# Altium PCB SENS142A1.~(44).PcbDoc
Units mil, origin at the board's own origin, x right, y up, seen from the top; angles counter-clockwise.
Board outline 2760 x 2518.85 mil, 4 copper layers (Top Layer, Signal Layer 1, Signal Layer 2, Bottom Layer), stack 62.2 mil thick; 50 components, 21 nets, 98 pads, 340 vias.
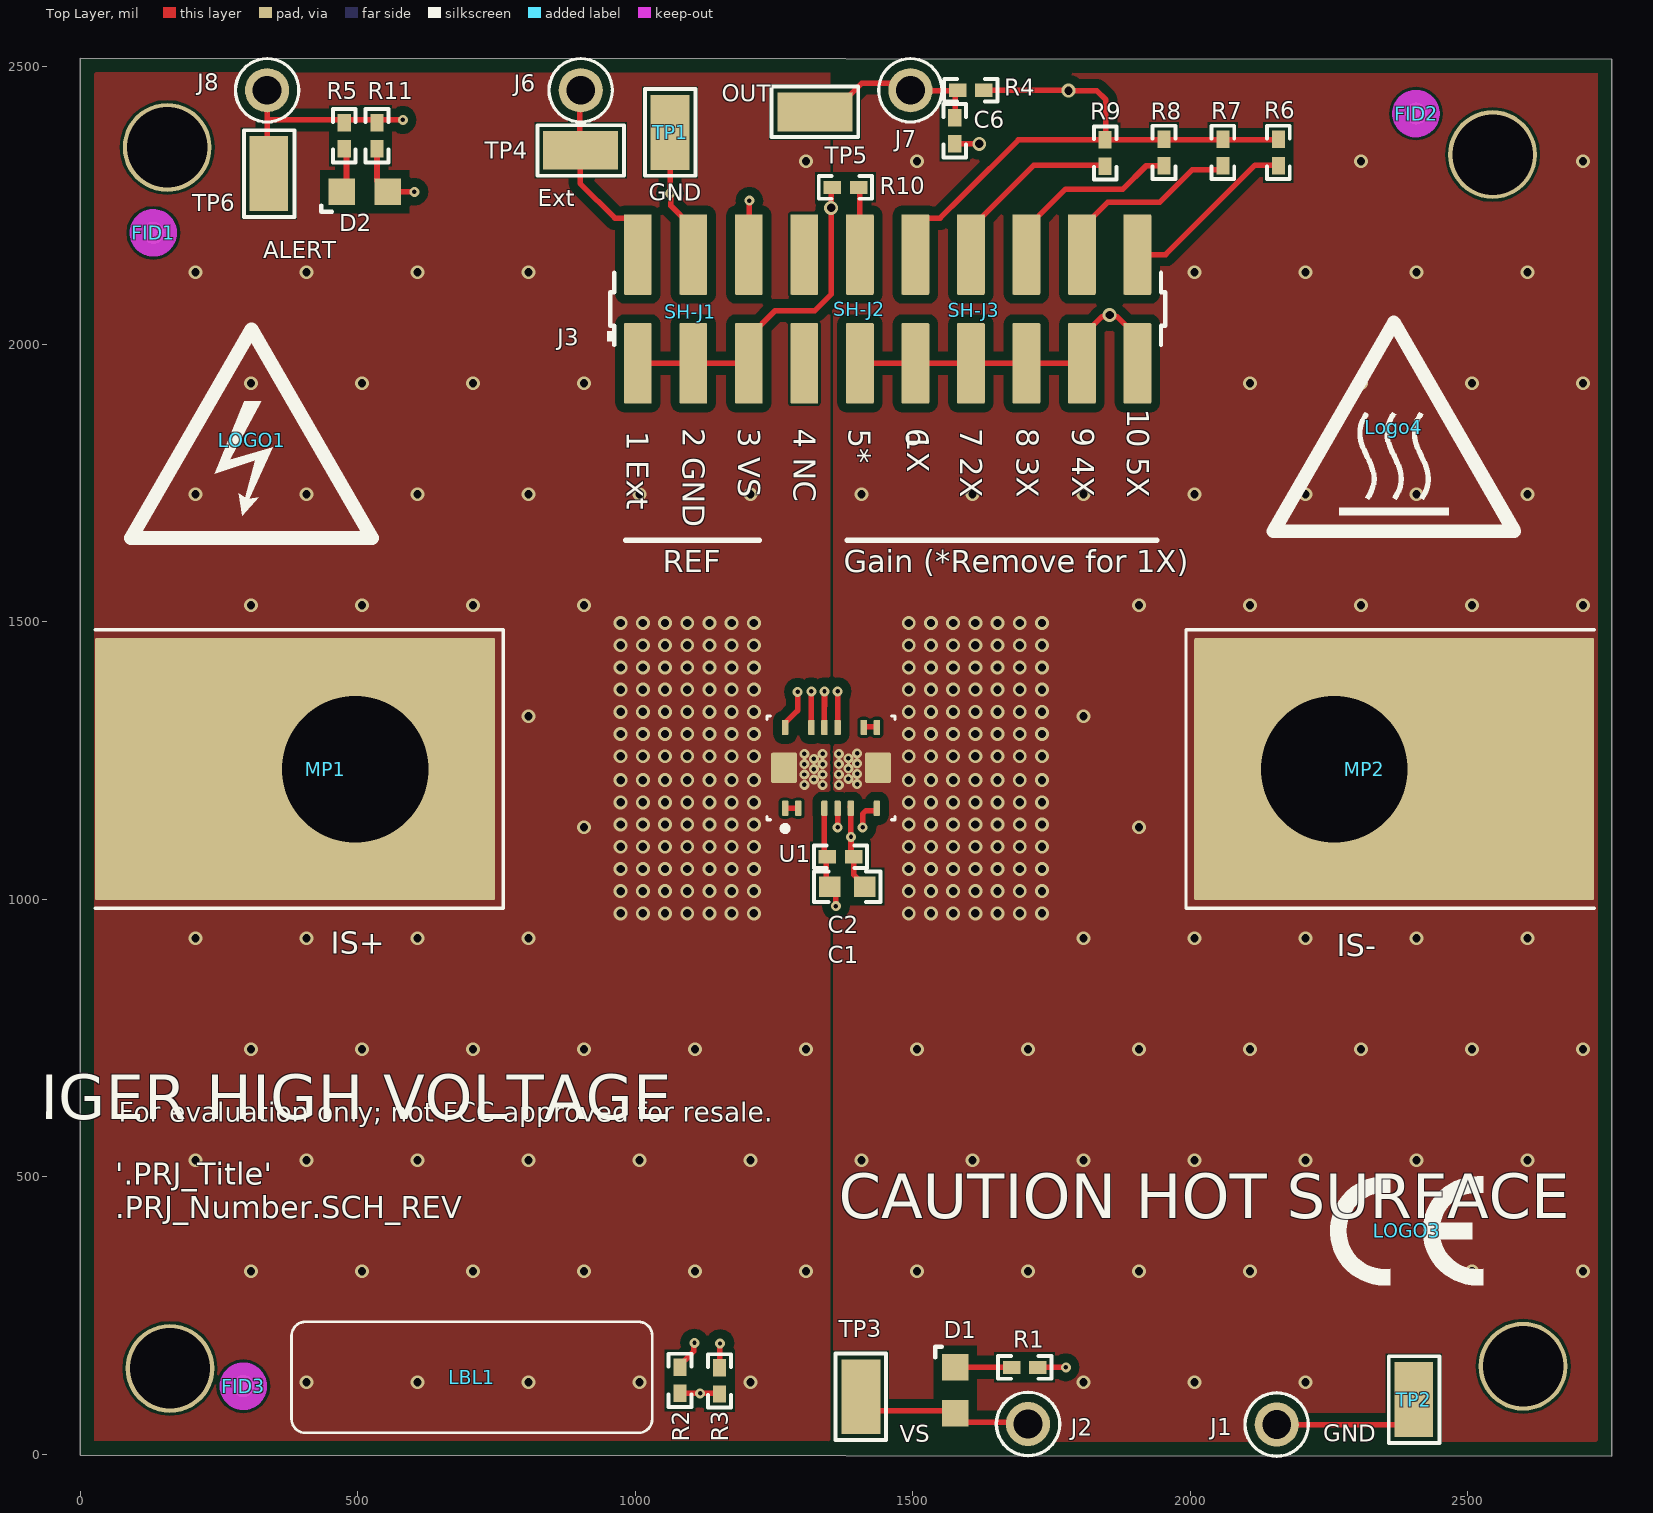
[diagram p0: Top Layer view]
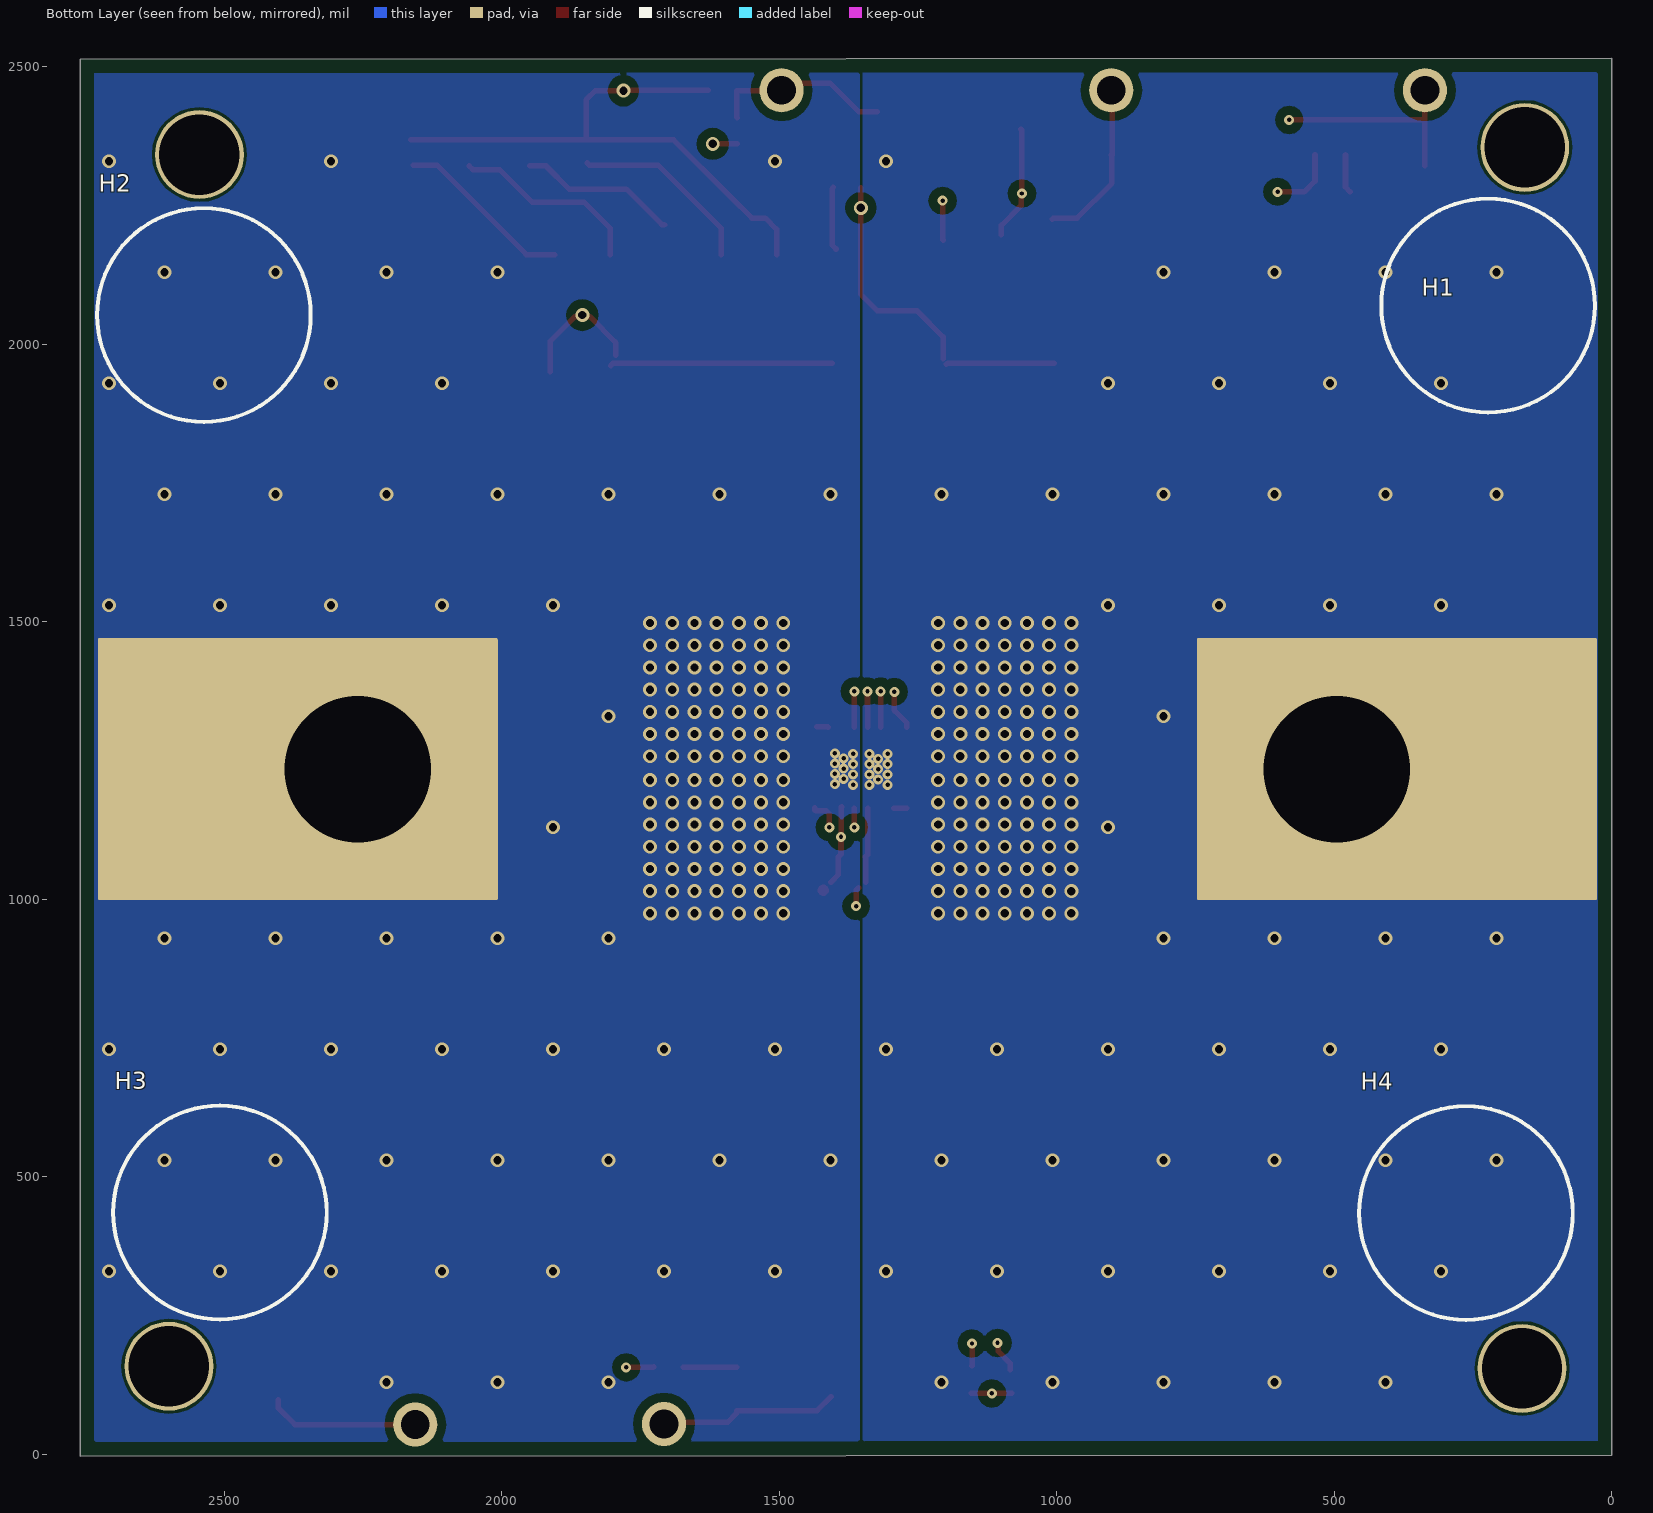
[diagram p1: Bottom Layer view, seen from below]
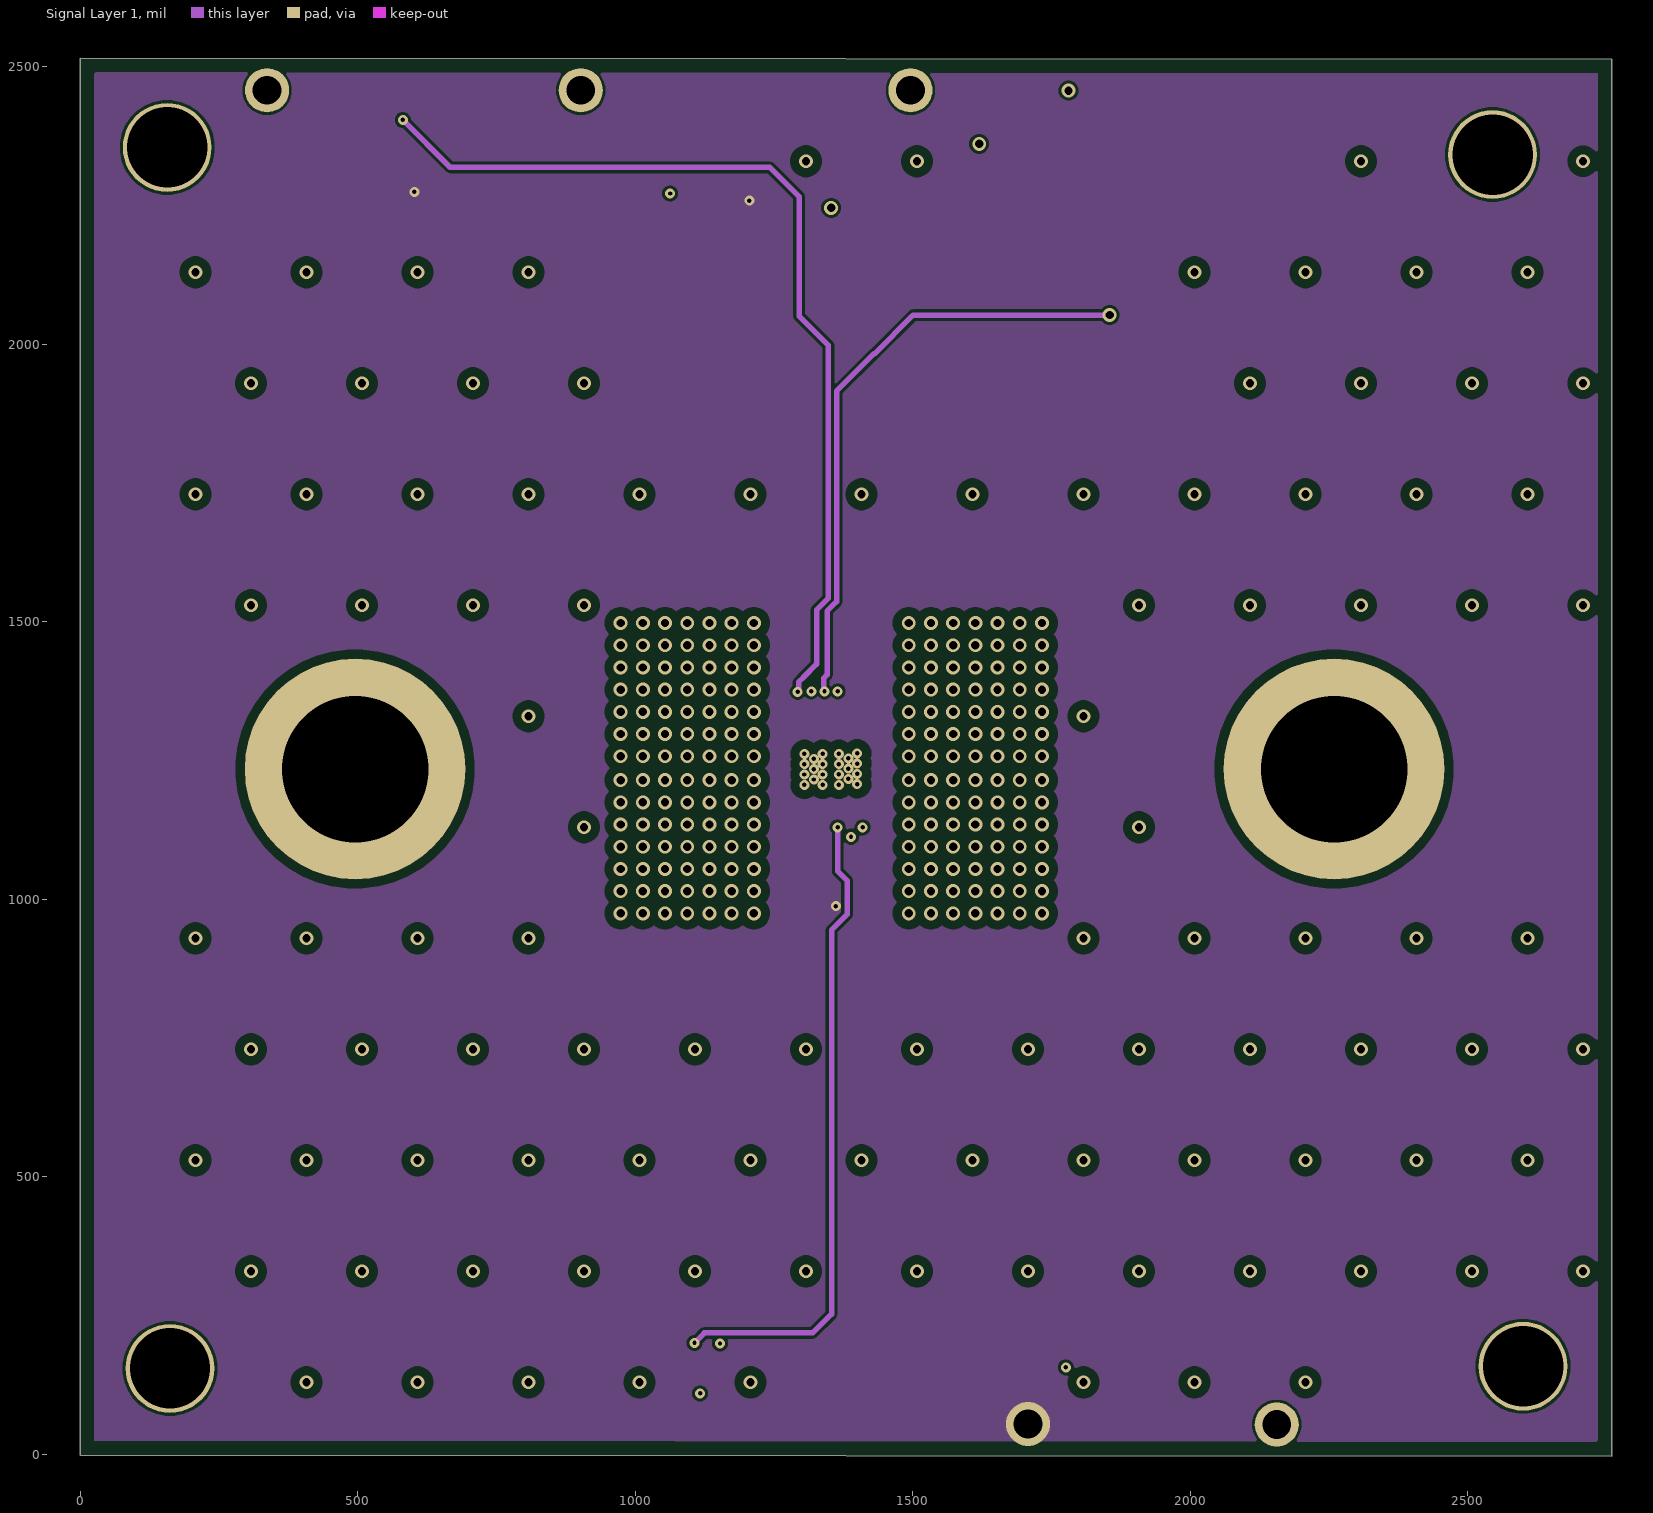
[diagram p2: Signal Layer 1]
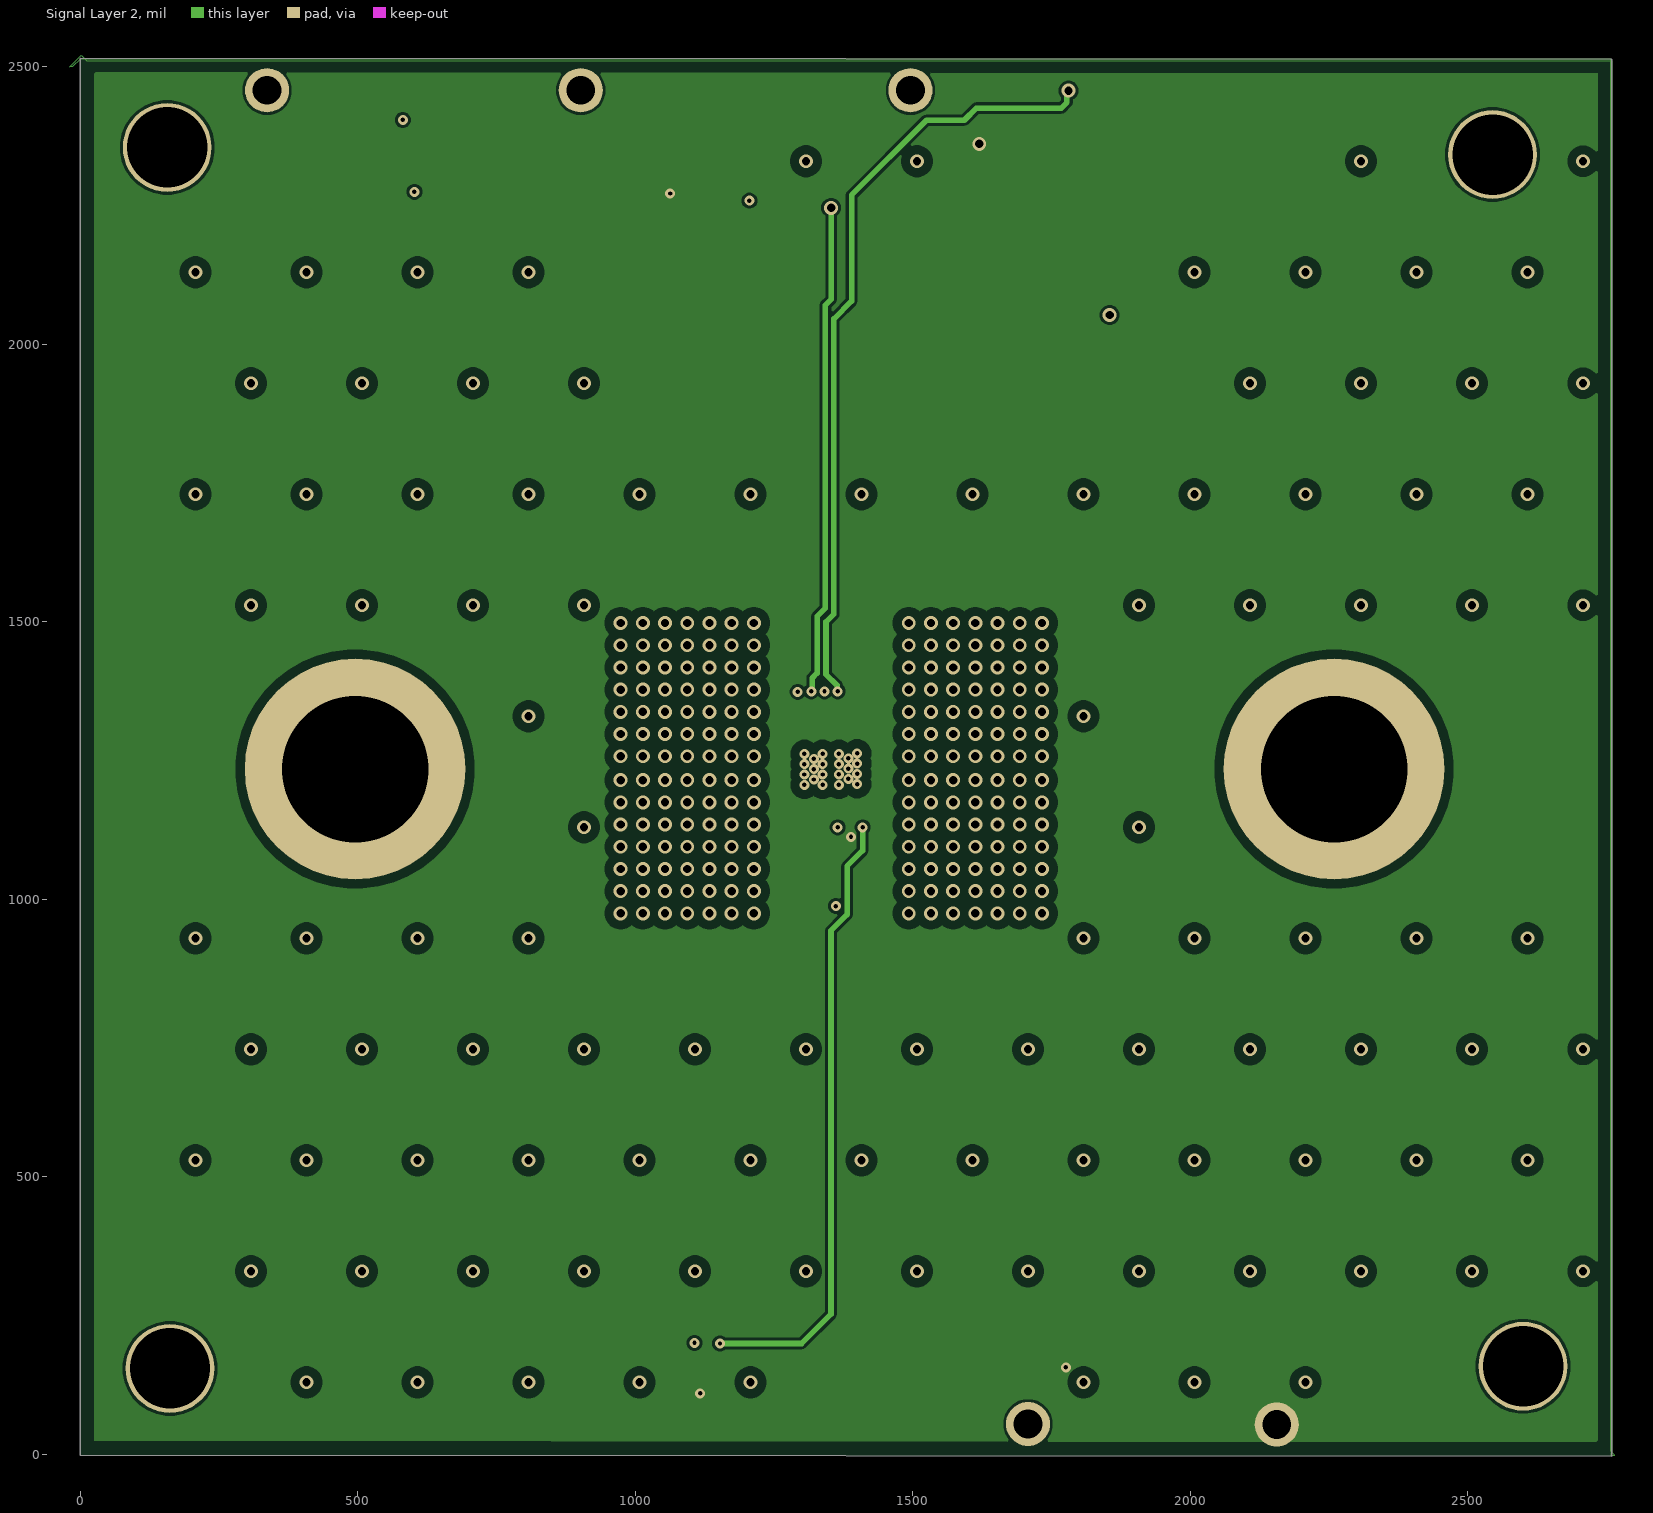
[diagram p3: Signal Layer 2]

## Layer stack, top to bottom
Top Solder: solder mask 0.4, Solder Resist, Dk 3.5
Top Layer: signal copper 2.8
Dielectric1: dielectric 17, FR-4, Dk 4.2
Signal Layer 1: signal copper 2.8
Dielectric 2: core 17, FR-4, Dk 4.2
Signal Layer 2: signal copper 2.8
Dielectric 3: dielectric 17, FR-4, Dk 4.2
Bottom Layer: signal copper 2.8
Bottom Solder: solder mask 0.4, Solder Resist, Dk 3.5

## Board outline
0,-1 0,2516 2760,2514.15 2760,-2.85

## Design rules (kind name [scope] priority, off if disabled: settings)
AcuteAngle [All] p1: minimum=4.50000000000000E+0001 checktracksonly=FALSE
AssemblyTestPointUsage [All] p1: valid=2
BoardOutlineClearance BoardOutlineClearance_MountingHoles [OnCopper and InComponentClass('Mounting Holes')] p1: gap=14 ignorepadtopadclearanceinfootprint=FALSE
BoardOutlineClearance BoardOutlineClearance_Poly [OnCopper and IsPoly] p2: gap=25 ignorepadtopadclearanceinfootprint=FALSE
BoardOutlineClearance [OnCopper and Not InComponentClass('Logo') and not InComponentClass('FiducialMark') and not InRegion(1000,500,4000,800) and not InPoly] p3: gap=15 ignorepadtopadclearanceinfootprint=FALSE
Clearance Clearance_Keepouts [((IsTrack Or IsArc) And Not InPoly) And IsFree and IsKeepOut vs ((IsTrack Or IsArc) And Not InPoly) And IsFree and IsKeepOut] p1: gap=0 ignorepadtopadclearanceinfootprint=FALSE
Clearance Clearance_IS+ [InNet('IS+') vs (InNet('OUT') OR InNet('FB') OR InNet('REF') OR InNet('GND') OR InNet('VS') OR InNet('NC4') OR InNet('NC6') OR InNet('ALERT') OR InNet('NetD1_2') OR InNet('NetD2_2') OR InNet('NetJ3_10') OR InNet('NetJ3_14') OR InNet('NetJ3_16') OR InNet('NetJ3_18') OR InNet('NetJ3_20') OR InNet('OUT_FLT') OR InNet('Ext_REF'))] p2: gap=16 ignorepadtopadclearanceinfootprint=TRUE
Clearance Clearance_IS- [InNet('IS-') vs (InNet('OUT') OR InNet('FB') OR InNet('REF') OR InNet('GND') OR InNet('VS') OR InNet('NC4') OR InNet('NC6') OR InNet('ALERT') OR InNet('NetD1_2') OR InNet('NetD2_2') OR InNet('NetJ3_10') OR InNet('NetJ3_14') OR InNet('NetJ3_16') OR InNet('NetJ3_18') OR InNet('NetJ3_20') OR InNet('OUT_FLT') OR InNet('Ext_REF'))] p3: gap=16 ignorepadtopadclearanceinfootprint=TRUE
Clearance Clearance_FiducialMark [IsKeepOut and InComponentClass('FiducialMark') vs IsPad and InComponentClass('FiducialMark')] p4: gap=0 ignorepadtopadclearanceinfootprint=FALSE
Clearance [All] p5: gap=5 ignorepadtopadclearanceinfootprint=TRUE
ComponentClearance ComponentClearance_MountingHoles_FiducialMarks [InComponentClass('Mounting Holes') vs InComponentClass('FiducialMark')] p1: gap=50 collisioncheckmode=3 verticalgap=10 showdistances=FALSE
ComponentClearance ComponentClearance_Shunt [InComponentClass('Header') vs InComponentClass('Shunt')] p2: gap=0 collisioncheckmode=3 verticalgap=0 showdistances=FALSE
ComponentClearance ComponentClearance_Logo [InComponentClass('Logo')] p3: gap=20 collisioncheckmode=3 verticalgap=10 showdistances=FALSE
ComponentClearance ComponentClearance_ScrewToNut [(HasFootprint('NY PMS 440 0025 PH')) vs (HasFootprint('Keystone_1902C'))] p4: gap=5 collisioncheckmode=3 verticalgap=10 showdistances=FALSE
ComponentClearance ComponentClearance_MountingHoles [InComponentClass('Mounting Holes')] p5: gap=250 collisioncheckmode=3 verticalgap=100000 showdistances=FALSE
ComponentClearance ComponentClearance_SmallPassives [HasFootprint('0201*') or HasFootprint('0402*') or HasFootprint('0508') or HasFootprint('0603*') or HasFootprint('0612') or HasFootprint('0805*') or HasFootprint('0815*') or HasFootprint('0830*') or HasFootprint('1206*') or HasFootprint('1210*') or HasFootprint('1808*') or HasFootprint('1812*') or HasFootprint('1825*') or HasFootprint('2010*') or HasFootprint('2220*') or HasFootprint('2225*') or HasFootprint('2512*') or HasFootprint('2728*') or HasFootprint('3518*') vs HasFootprint('0201*') or HasFootprint('0402*') or HasFootprint('0508') or HasFootprint('0603*') or HasFootprint('0612') or HasFootprint('0805*') or HasFootprint('0815*') or HasFootprint('0830*') or HasFootprint('1206*') or HasFootprint('1210*') or HasFootprint('1808*') or HasFootprint('1812*') or HasFootprint('1825*') or HasFootprint('2010*') or HasFootprint('2220*') or HasFootprint('2225*') or HasFootprint('2512*') or HasFootprint('2728*') or HasFootprint('3518*')] p6: gap=14.96 collisioncheckmode=3 verticalgap=10 showdistances=FALSE
ComponentClearance ComponentClearance_THtoSMT [IsThruComponent vs IsSMTComponent] p7: gap=40 collisioncheckmode=3 verticalgap=30 showdistances=FALSE
ComponentClearance ComponentClearance_THtoTH [IsThruComponent vs IsThruComponent] p8: gap=30 collisioncheckmode=3 verticalgap=30 showdistances=FALSE
ComponentClearance [All] p9: gap=30 collisioncheckmode=3 verticalgap=10 showdistances=FALSE
DiffPairsRouting [All] p1: maxlimit=100 minlimit=10 mostfreqgap=10 toplayer_minwidth=15 toplayer_maxwidth=15 toplayer_prefwidth=15 midlayer1_minwidth=15 midlayer1_maxwidth=15 midlayer1_prefwidth=15 midlayer2_minwidth=15 midlayer2_maxwidth=15 midlayer2_prefwidth=15 bottomlayer_minwidth=15 bottomlayer_maxwidth=15 bottomlayer_prefwidth=15 maxuncoupledlength=1000
FabricationTestPointUsage TestPointUsage [All] p1: valid=2 allowmultiple=FALSE
FabricationTestpoint Testpoint [All] p1: side=3 testpointundercomponent=TRUE minsize=40 maxsize=100 preferedsize=60 minholesize=0 maxholesize=40 preferedholesize=32 testpointgrid=1 allowsidetop=TRUE allowsidebottom=TRUE usegrid=TRUE gridtolerance=0.01
FanoutControl Fanout_LCC [IsLCC] p1: bgadir=Out bgaviamode=Centered fanoutstyle=Auto fanoutdirection=Alternating viagrid=1 // Fanout_LCC (Default Rule)
FanoutControl Fanout_BGA [IsBGA] p2: bgadir=Out bgaviamode=Centered fanoutstyle=Auto fanoutdirection=Alternating viagrid=1 // Fanout_BGA (Default Rule)
FanoutControl Fanout_Default [All] p4: bgadir=Out bgaviamode=Centered fanoutstyle=Auto fanoutdirection=Alternating viagrid=1 // Fanout_Default (Default Rule)
FanoutControl Fanout_Small [(CompPinCount < 5)] p5: bgadir=Out bgaviamode=Centered fanoutstyle=Auto fanoutdirection=OutThenIn viagrid=1 // Fanout_Small (Default Rule)
HoleSize [All] p1: absolutevalues=TRUE maxlimit=251 minlimit=8 maxpercent=80.000 minpercent=20.000
HoleToHoleClearance [All] p1: gap=8 allowstackedmicrovias=TRUE
MinimumAnnularRing MinimumAnnularRing_ThermalPadVias [IsVia and InAnyComponent] p1: minimumring=5
MinimumAnnularRing [All] p2: minimumring=5
MinimumSolderMaskSliver MinimumSolderMaskSliver_Logo [InComponentClass('Logo') vs InComponentClass('Logo')] p1: minsoldermaskwidth=0.7
MinimumSolderMaskSliver [All] p2: minsoldermaskwidth=4
PlaneConnect [All] p1: planeconnectstyle=Relief reliefexpansion=10 reliefentries=4 reliefconductorwidth=10 reliefairgap=10
PolygonConnect PolygonConnect_Trace [InNet('NetJ1_5') OR InNet('NetJ1_3')] p1: connectstyle=Direct reliefconductorwidth=10 reliefentries=4 polygonreliefangle="90 Angle" airgapwidth=10
PolygonConnect [All] p2: thpad.connectstyle=Direct thpad.reliefconductorwidth=10 thpad.reliefentries=4 thpad.polygonreliefangle="90 Angle" thpad.airgapwidth=10 smdpad.connectstyle=Relief smdpad.reliefconductorwidth=10 smdpad.reliefentries=2 smdpad.polygonreliefangle="90 Angle" smdpad.airgapwidth=10 via.connectstyle=Direct via.reliefconductorwidth=10 via.reliefentries=4 via.polygonreliefangle="90 Angle" via.airgapwidth=10
RoutingVias [All] p1: holewidth=10 width=20 viastyle="Through Hole" minholewidth=4 minwidth=15 maxholewidth=40 maxwidth=65
SilkToBoardRegionClearance [Not ((IsComment or IsDesignator) And (Hide <> 'False')) and not InRegion(1000,500,4000,800)] p1:
SilkToSilkClearance SilkToSilkClearance_Pb-FreeLogo [(HasFootprint('Pb-Free_Overlay_Medium') OR HasFootprint('Pb-Free_Overlay_Small')) vs (HasFootprint('Pb-Free_Overlay_Medium') OR HasFootprint('Pb-Free_Overlay_Small'))] p1: silktosilkclearance=0
SilkToSilkClearance [All] p2: silktosilkclearance=3.94
SilkToSolderMaskClearance SilkToComponentPadClearance [(IsPad or IsFill or IsRegion) and InAnycomponent] p1: minsilkscreentomaskgap=5 clearancetoexposedcopper=TRUE
SilkToSolderMaskClearance "Silk to Solder Mask Opening" [All] p2: minsilkscreentomaskgap=3.94 clearancetoexposedcopper=FALSE
SolderMaskExpansion [All] p1: expansion=1.97 istentingtop=FALSE
UnRoutedNet [All] p1: checkbadconnections=TRUE
Width [All] p1: maxlimit=100 minlimit=5 preferedwidth=10 checkconnectedcopper=TRUE
13 further rules are at their usual default settings.

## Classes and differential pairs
component class Label: LBL1
component class Shunt: SH-J1 SH-J2 SH-J3
component class Header: J3
component class SENS142A1: "ALERT BUS" C1 C2 C6 D1 D2 J1 J2 J3 J6 J7 J8 MP1 MP2 q R1 R2 R3 R4 R5 R6 R7 R8 R9 R10 R11 SH-J1 SH-J2 SH-J3 SW2 SW? TP1 TP2 TP3 TP4 TP5 TP6 U1
component class SENS142A1_HW: FID1 FID2 FID3 H1 H2 H3 H4 LBL1 LOGO1 Logo2 LOGO3 Logo4 ZZ1 ZZ2 ZZ3 ZZ4
component class FiducialMark: FID1 FID2 FID3
component class AssemblyNote: ZZ1 ZZ2 ZZ3 ZZ4

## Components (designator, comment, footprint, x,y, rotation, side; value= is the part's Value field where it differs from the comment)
C1 "C1608X6S1H105K080AC" 0603 1382.19,1023 r0 top value=1uF
C2 "GRM155R71H104ME14D" 0402 1370,1077 r0 top value=0.1uF
C6 "CGA2B3X7S2A103K050BB" 0402 1576,2385 r90 top value=0.01uF
D1 "POWER" VAOL-0805_White 1577,115.66 r90 top
D2 "ALERT" VAOL-0805_White 513,2275 r180 top
FID1 "Fiducial" Fiducial10-20 132,2201.12 r0 top
FID2 "Fiducial" Fiducial10-20 2407,2416 r0 top
FID3 "Fiducial" Fiducial10-20 294,123 r0 top
H1 "SJ61A2" Bumpon_SJ61A2 223,2070 r180 bottom
H2 "SJ61A2" Bumpon_SJ61A2 2537,2053 r180 bottom
H3 "SJ61A2" Bumpon_SJ61A2 2508,436 r180 bottom
H4 "SJ61A2" Bumpon_SJ61A2 263,435 r180 bottom
J1 "" FP-3-331272-8_PIN_RCPT-MFG 2156,54 r0 top
J2 "" FP-3-331272-8_PIN_RCPT-MFG 1708,55 r180 top
J3 "TSM-110-01-L-DV-P" CONN_TSM-110-01-T-DV-P 1455,2064 r90 top
J6 "" FP-3-331272-8_PIN_RCPT-MFG 902,2458 r0 top
J7 "" FP-3-331272-8_PIN_RCPT-MFG 1496,2458 r0 top
J8 "" FP-3-331272-8_PIN_RCPT-MFG 337,2458 r0 top
LBL1 "THT-14-423-10" Label_650x200 706,139 r180 top
LOGO1 "DANGER HIGH VOLTAGE" IEC_HighVoltage_Medium 309,1827 r0 top
Logo2 "FCC disclaimer" FCC_disclaimer 3340,617.12 r90 top
LOGO3 "CE Mark" CE_Mark_5mm 2390,403 r0 top
Logo4 "CAUTION HOT SURFACE" IEC_HotSurface_Medium 2367,1851 r0 top
MP1 "CB70-14-190" FP-CB70-14-190_CONN_TERM_RECT_LUG-MFG -30,1235 r0 top
MP2 "CB70-14-190" FP-CB70-14-190_CONN_TERM_RECT_LUG-MFG 2785,1235 r180 top
R1 "CRCW040210K0FKED" 0402 1702,157 r180 top value=10.0k
R2 "RC0402JR-070RL" 0402 1081,133.62 r270 top value=0
R3 "RC0402JR-070RL" 0402 1152,132.62 r270 top value=0
R4 "RC0402JR-070RL" 0402 1605,2458 r180 top value=0
R5 "CRCW040210K0FKED" 0402 476,2376 r90 top value=10.0k
R6 "CRCW040220K0FKED" 0402 2159,2346 r270 top value=20.0k
R7 "CRCW040215K0FKED" 0402 2059,2346 r270 top value=15.0k
R8 "CRCW040210K0FKED" 0402 1953,2346 r90 top value=10.0k
R9 "CRCW04024K99FKED" 0402 1847,2345 r270 top value=4.99k
R10 "CRCW04024K99FKED" 0402 1379,2283 r0 top value=4.99k
R11 "CRCW040210K0FKED" 0402 535,2376 r90 top value=10.0k
SH-J1 "SPC02SYAN" SPC02SYAN 1099,2059 r270 top value=1x2
SH-J2 "SPC02SYAN" SPC02SYAN 1404,2063 r90 top value=1x2
SH-J3 "SPC02SYAN" SPC02SYAN 1610,2062 r90 top value=1x2
TP1 "GND" Testpoint_Keystone_Miniature 1063,2382 r90 top
TP2 "GND" Testpoint_Keystone_Miniature 2403,99 r90 top
TP3 "VS" Testpoint_Keystone_Miniature 1407,104 r270 top
TP4 "Ext_REF" Testpoint_Keystone_Miniature 902,2350 r0 top
TP5 "OUT" Testpoint_Keystone_Miniature 1324,2419 r180 top
TP6 "" Testpoint_Keystone_Miniature 340,2308 r90 top
U1 "INA750AIREMR" REM0014B-MFG 1353,1237.12 r90 top
ZZ1 "This Assembly Note is for PCB labels only" AssemblyNoteLabel -115,3802.12 r0 top
ZZ2 "These assemblies are ESD sensitive, ESD precautions shall be observed." AssemblyNote -115,3693.24 r0 top
ZZ3 "These assemblies must be clean and free from flux and all contaminants. Use of no clean flux is not acceptable." AssemblyNote -115,3604.68 r0 top
ZZ4 "These assemblies must comply with workmanship standards IPC-A-610 Class 2, unless otherwise specified." AssemblyNote -115,3516.12 r0 top

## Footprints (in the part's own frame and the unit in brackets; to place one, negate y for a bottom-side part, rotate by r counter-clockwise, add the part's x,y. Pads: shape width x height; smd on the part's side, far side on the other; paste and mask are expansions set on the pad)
0402 [mm] "0402 from SM-752 data"
  rect 0.8x0.6 smd: 1(-0.6,0) 2(0.6,0)
  silkscreen extent -1.22,-0.52 1.22,0.52, body extent -0.55,-0.3 0.55,0.3, height 0.6
0603 [mm] "0603 from SM-752 data"
  rect 1x0.95 smd: 1(-0.8,0) 2(0.8,0)
  silkscreen extent -1.52,-0.69 1.52,0.69, body extent -0.87,-0.47 0.87,0.47, height 1
AssemblyNote [mil] "Assembly Note"
AssemblyNoteLabel [mil] "Assembly Note for PCB Labels"
Bumpon_SJ61A2 [mil] "3M Hemispherical Bumpon transparent"
  round 1 on Mech4: 0(0,0)
  silkscreen extent -192,-192 192,192, body extent -193,-193 193,193, height 250
CE_Mark_5mm [mil] "Minimum text height for CE Mark"
  silkscreen extent -138,-98 138,98
CONN_TSM-110-01-T-DV-P [mil]
  rrect8% 145x50 smd: 1(-98,450) 2(98,450) 3(-98,350) 4(98,350) 5(-98,250) 6(98,250) 7(-98,150) 8(98,150) 9(-98,50) 10(98,50) 11(-98,-50) 12(98,-50) 13(-98,-150) 14(98,-150) 15(-98,-250) 16(98,-250) 17(-98,-350) 18(98,-350) 19(-98,-450) 20(98,-450)
  silkscreen extent -65,-500 65,506, body extent -145,-500 145,500, height 380
FCC_disclaimer [mil]
Fiducial10-20 [mm]
  round 1 smd mask+0.5: 1(0,0)
  Top Layer keep-out circle w1.178: c0,0 r0.5
FP-3-331272-8_PIN_RCPT-MFG [mm]
  round 2.02 hole 1.32 paste-1000 mask+0: 1(0,0)
  silkscreen extent -1.45,-1.45 1.45,1.45, body extent -1.11,-1.11 1.11,1.11, height 0.25
FP-CB70-14-190_CONN_TERM_RECT_LUG-MFG [mm]
  rrect1% 18.3x12 smd paste-1000 mask+0: 1(10.6,0)
  rrect1% 18.3x12 smd far side paste-1000 mask+0: 1(10.6,0)
  round 10.1 hole 6.7 unplated paste+0 mask+0: 1(13.35,0)
  silkscreen extent 1.45,-6.38 20.12,6.38, body extent -20.1,-6.35 20.1,6.35, height 0.25
IEC_HighVoltage_Medium [mil]
  silkscreen extent -217,-176 217,200
IEC_HotSurface_Medium [mil]
  silkscreen extent -217,-188 217,188
Label_650x200 [mil] "Thermal Transfer Label"
  round 1 on Mech13: 0(0,0)
  silkscreen extent -325,-100 325,100, body extent -325,-100 325,100, height 1
REM0014B-MFG [mm]
  rrect33% 0.7x0.3 smd paste+0 mask+0: 1(-1.85,2.1) 2(-1.85,1.5) 3(-1.85,0.3) 4(-1.85,-0.3) 5(-1.85,-0.9) 6(-1.85,-2.1) 8(1.85,-2.1) 9(1.85,-1.5) 10(1.85,-0.3) 11(1.85,0.3) 12(1.85,0.9) 13(1.85,2.1)
  rrect17% 1.4x1.2 smd paste-1000 mask-1000: 7(0,-2.15) 14(0,2.15)
  silkscreen extent -2.9,-2.93 2.37,2.93, body extent -2.3,-2.85 2.3,2.85, height 0.25
SPC02SYAN [mil] "SULLINS"
  round 1 on Mech3: 0(0,0)
  body extent -98,-47 99,47, height 366
Testpoint_Keystone_Miniature [mil] "Miniature SMT test point"
  rect 135x70 smd: 1(0,0)
  silkscreen extent -78,-46 78,45, body extent -52,-20 52,20, height 61
VAOL-0805_White [mm] "Visual Communications"
  rect 1.2x1.2 smd: 1(-1.05,0) 2(1.05,0)
  silkscreen extent 1.5,0.63 2,0.91, body extent -1.05,-0.67 1.05,0.67, height 1.1

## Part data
C1: library part CMP-0007029-4, "CAP, CERM, 1 uF, 50 V, +/- 10%, X6S, 0603", Cap_Case=0603, Manufacturer=TDK, Supplier Part Number 1=445-7424-1-ND, TempCo=X6S, Tolerance_%=10%, Value1="0.005522 ohm", Value2=50V, ValueDisplayed=1uF
C2: library part CMP-0006675-2, "CAP, CERM, 0.1 uF, 50 V, +/- 20%, X7R, 0402", Cap_Case=0402, Manufacturer=MuRata, Supplier Part Number 1=490-10701-1-ND, TempCo=X7R, Tolerance_%=20%, Value1=Unknown, Value2=50V, ValueDisplayed=0.1uF
C6: library part CMP-0006333-1, "CAP, CERM, 0.01 uF, 100 V, +/- 10%, X7S, AEC-Q200 Grade 1, 0402", Cap_Case=0402, Manufacturer=TDK, Supplier Part Number 1=445-6910-1-ND, TempCo=X7S, Tolerance_%=10%, Value1="0.410191 ohm", Value2=100V, ValueDisplayed=0.01uF
D1 D2: library part CMP-0002885-2, "LED, White, SMD", Color=White, Manufacturer="Visual Communications Company, LLC", PartNumber=VAOL-S8WR4, Value1=W, Value2=2.925V
FID1 FID2 FID3: library part CMP-0077181-1, "Fiducial mark.  There is nothing to buy or mount.", Manufacturer=N/A
H1 H2 H3 H4: library part CMP-0003622-1, "Bumpon, Hemisphere, 0.375 X 0.235, Black", Manufacturer=3M, Supplier Part Number 1=SJ5748-0-ND
J1 J2 J6 J7 J8: library part CMP-0086763-1, "CONN PIN RCPT .018-.021 SOLDER", Current_A=5A, Manufacturer="TE Connectivity", PartNumber=3-331272-8
J3: library part CMP-0075600-2, "Header, 2.54mm, 10x2, Gold, SMT", Color=Black, Current_A=5.4A, Manufacturer=Samtec, Supplier Part Number 1=SAM8739-ND, Voltage_V=475V
LBL1: library part CMP-0003625-1, "Thermal Transfer Printable Labels, 0.650\" W x 0.200\" H - 10,000 per roll", Manufacturer=Brady, Supplier Part Number 1=97C5133
LOGO1: library part CMP-0074835-1, "IEC 61010-1 High Voltage Warning"
Logo2: library part CMP-0074847-1, "FCC_disclaimer"
LOGO3: library part CMP-0074844-1
Logo4: library part CMP-0074837-2, "IEC 61010-1 Hot Surface Warning", Manufacturer="Texas Instruments"
MP1 MP2: library part CMP-0121463-2, "Terminal Connector Rectangular Lug, Grounding 1/4 Stud", Current_A=90A, Digikey Part Number=298-CB70-14-190-ND, Manufacturer=Panduit, Operating Temperature Range="to +90°C", Voltage_V=600V
R1 R5 R8 R11: library part CMP-0025958-3, "RES, 10.0 k, 1%, 0.063 W, AEC-Q200 Grade 0, 0402", Manufacturer=Vishay-Dale, Power_W=63mW, Supplier Part Number 1=541-10.0KLCT-ND, TempCo="100 ppm/C", Tolerance_%=1%, Value2=0.063W, Value_Code=10k0, ValueDisplayed=10.0k
R2 R3 R4: library part CMP-0027004-2, "RES, 0, 5%, 0.063 W, 0402", Manufacturer="Yageo America", Power_W=63mW, Supplier Part Number 1=311-0.0JRCT-ND, TempCo="200 ppm/C", Tolerance_%=5%, Value2=0.063W, Value_Code=0000, ValueDisplayed=0
R6: library part CMP-0026162-1, "RES, 20.0 k, 1%, 0.063 W, 0402", Manufacturer=Vishay-Dale, Power_W=63mW, Supplier Part Number 1=541-20.0KLCT-ND, TempCo="100 ppm/C", Tolerance_%=1%, Value2=0.063W, Value_Code=20k0, ValueDisplayed=20.0k
R7: library part CMP-0026027-2, "RES, 15.0 k, 1%, 0.063 W, 0402", Manufacturer=Vishay-Dale, Power_W=63mW, Supplier Part Number 1=541-15.0KLCT-ND, TempCo="100 ppm/C", Tolerance_%=1%, Value2=0.063W, Value_Code=15k0, ValueDisplayed=15.0k
R9 R10: library part CMP-0026414-1, "RES, 4.99 k, 1%, 0.063 W, 0402", Manufacturer=Vishay-Dale, Power_W=63mW, Supplier Part Number 1=541-4.99KLCT-ND, TempCo="100 ppm/C", Tolerance_%=1%, Value2=0.063W, Value_Code=4k99, ValueDisplayed=4.99k
SH-J1 SH-J2 SH-J3: library part CMP-0003642-1, "Shunt, 100mil, Flash Gold, Black", Manufacturer="Sullins Connector Solutions", Supplier Part Number 1=S9001-ND
TP1 TP2 TP3 TP4 TP5 TP6: library part CMP-0055152-1, "Test Point, Miniature, SMT", Manufacturer=Keystone, PartNumber=5015, Supplier Part Number 1=36-5015TR-ND
U1: library part CMP-0122809-2, "-4V to 110V, Bidirectional, Ultra-Precise, Current Sense Amplifier with Enhanced PWM Rejection and 35A EZShuntTM Technology", Input Offset Voltage=65mV, Manufacturer="Texas Instruments", Max Supply Voltage=5.5V, Min Supply Voltage=2.7V, Nominal Supply Current=3.5mA, Operating Temperature Range="-55°C to +150°C", Output Current Per Channel=25A
ZZ1: library part CMP-0003616-3
ZZ2: library part CMP-0077236-1
ZZ3: library part CMP-0077237-1
ZZ4: library part CMP-0077238-1

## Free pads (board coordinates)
  round 160 hole 145: 3(157,2355) 3(162,155) 3(2545,2342.12) 3(2600,159)

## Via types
v1: diameter 25, hole 15, Top Layer to Bottom Layer, tented both sides, 302 vias
v2: diameter 18, hole 8, Top Layer to Bottom Layer, tented both sides, 38 vias

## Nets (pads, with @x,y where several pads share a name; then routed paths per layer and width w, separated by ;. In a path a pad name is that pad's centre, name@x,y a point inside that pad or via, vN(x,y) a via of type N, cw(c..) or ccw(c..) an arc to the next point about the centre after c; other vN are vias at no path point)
ALERT: J8.1 R5.2 R11.2 TP6.1 U1.13 | length 2150.9
  Top Layer w10: TP6.1@337,2322 337,2406 ; J8.1@337,2446 337,2406 ; v2(581.45,2404.5) 338.5,2404.5 337,2406 ; U1.13 1270.32,1317.83 1293,1340.51 1293,1348 ; v2(1293,1374) 1293.26,1373.74 1293.26,1348
  Signal Layer 1 w10: v2(581.45,2404.5) 666.95,2319 1243,2319 1295.59,2266.41 1295.59,2050.97 1348.19,1998.38 1348.19,1543 1327,1521.81 1327,1424.25 1303.87,1401.13 ; v2(1293,1374) 1294.53,1375.53 1294.53,1391.53 1304,1401
Ext_REF: J3.2 J6.1 TP4.1 | length 301.7
  Top Layer w10: TP4.1@900,2342 J6.1@900,2458 ; TP4.1@902,2342 901,2341 901,2290.32 963.82,2227.5 1006.5,2227.5 J3.2@1008,2226
FB: J3.9 J3.11 J3.13 J3.15 J3.17 J3.19 U1.11 | length 1826
  Top Layer w10: v2@1341,1376 1341.2,1375.8 U1.11@1341.2,1309.97 ; 1341.22,1349.33 v2(1341.22,1375) ; J3.9 J3.11 J3.13 J3.15 1800,1966 J3.17@1804,1962 ; J3.17@1795,1981 1795,2003.5 1841.63,2050.13 1852.13,2050.13 v1(1855,2053) 1857.87,2050.13 1868.37,2050.13 1913,2005.5 J3.19@1913,1951
  Signal Layer 1 w10: v2@1341,1376 1340,1377 1340,1399 1346,1405 1346,1519.59 1363.19,1536.78 1363.19,1916.19 1430.5,1983.5 ; 1431,1983 1501,2053 v1(1855,2053)
GND: C1.2 C2.2 C6.1 J1.1 J3.4 R1.1 R2.2 R3.2 TP1.1 TP2.1 U1.5 | length 794.1
  Top Layer w10: TP1.1@1065,2388 1063,2386 TP1.1 v2(1063,2272) 1064.53,2270.47 1064.53,2249.97 1100,2214.5 J3.4@1100,2198 ; R2.2 v2(1117,110) R3.2@1154,110 ; U1.5@1388,1167 1388.72,1166.28 1388.72,1113.28 v2(1389,1113) 1389,1081.62 C2.2 1393.62,1044.7 1407.32,1031 C1.2@1407.5,1031 ; C6.1 v1(1620,2361.38) ; R1.1@1726,158 1727,157 v2@1777,157 ; J1.1 2373,54 2403,84 TP2.1
  Top Layer w20: C1.2@1421,1016.68 C1.2@1421.66,1017.35
  other v2: 1776,157
IN+: U1.1 U1.2 | length 23.8
  Top Layer w10: U1.1 1293.71,1164.29 U1.2@1294,1164
IN-: U1.8 U1.9 | length 21.5
  Top Layer w10: U1.9 1412.05,1310.09 1412.96,1311 U1.8@1433,1311
IS+: MP1.1 U1.14
  other v1: 408,130.12 608,130.12 808,130.12 1008,130.12 1208,130.12 308,330.12 508,330.12 708,330.12 908,330.12 1108,330.12 1308,330.12 208,530.12 408,530.12 608,530.12 808,530.12 1008,530.12 1208,530.12 308,730.12 508,730.12 708,730.12 908,730.12 1108,730.12 1308,730.12 208,930.12 408,930.12 608,930.12 808,930.12 974,975 1014,975 1054,975 1094,975 1134,975 1174,975 1214,975 974,1015 1014,1015 1054,1015 1094,1015 1134,1015 1174,1015 1214,1015 974,1055 1014,1055 1054,1055 1094,1055 1134,1055 1174,1055 1214,1055 974,1095 1014,1095 1054,1095 1094,1095 1134,1095 1174,1095 1214,1095 908,1130.12 974,1135 1014,1135 1054,1135 1094,1135 1134,1135 1174,1135 1214,1135 974,1175 1014,1175 1054,1175 1094,1175 1134,1175 1174,1175 1214,1175 974,1215 1014,1215 1054,1215 1094,1215 1134,1215 1174,1215 1214,1215 974,1258 1014,1258 1054,1258 1094,1258 1134,1258 1174,1258 1214,1258 974,1298 1014,1298 1054,1298 1094,1298 1134,1298 1174,1298 1214,1298 808,1330.12 974,1338 1014,1338 1054,1338 1094,1338 1134,1338 1174,1338 1214,1338 974,1378 1014,1378 1054,1378 1094,1378 1134,1378 1174,1378 1214,1378 974,1418 1014,1418 1054,1418 1094,1418 1134,1418 1174,1418 1214,1418 974,1458 1014,1458 1054,1458 1094,1458 1134,1458 1174,1458 1214,1458 974,1498 1014,1498 1054,1498 1094,1498 1134,1498 1174,1498 1214,1498 308,1530.12 508,1530.12 708,1530.12 908,1530.12 208,1730.12 408,1730.12 608,1730.12 808,1730.12 1008,1730.12 1208,1730.12 308,1930.12 508,1930.12 708,1930.12 908,1930.12 208,2130.12 408,2130.12 608,2130.12 808,2130.12 1308,2330.12
  other v2: 1305.08,1206.64 1338.08,1206.64 1322.08,1216.21 1305.08,1225.21 1338.08,1225.21 1322.08,1234.78 1305.08,1243.78 1338.08,1243.78 1322.08,1253.36 1305.08,1262.36 1338.08,1262.36
IS-: MP2.1 U1.7
  other v1: 1808,130.12 2008,130.12 2208,130.12 1508,330.12 1708,330.12 1908,330.12 2108,330.12 2308,330.12 2508,330.12 2708,330.12 1408,530.12 1608,530.12 1808,530.12 2008,530.12 2208,530.12 2408,530.12 2608,530.12 1508,730.12 1708,730.12 1908,730.12 2108,730.12 2308,730.12 2508,730.12 2708,730.12 1808,930.12 2008,930.12 2208,930.12 2408,930.12 2608,930.12 1493,975 1533,975 1573,975 1613,975 1653,975 1693,975 1733,975 1493,1015 1533,1015 1573,1015 1613,1015 1653,1015 1693,1015 1733,1015 1493,1055 1533,1055 1573,1055 1613,1055 1653,1055 1693,1055 1733,1055 1493,1095 1533,1095 1573,1095 1613,1095 1653,1095 1693,1095 1733,1095 1908,1130.12 1493,1135 1533,1135 1573,1135 1613,1135 1653,1135 1693,1135 1733,1135 1493,1175 1533,1175 1573,1175 1613,1175 1653,1175 1693,1175 1733,1175 1493,1215 1533,1215 1573,1215 1613,1215 1653,1215 1693,1215 1733,1215 1493,1258 1533,1258 1573,1258 1613,1258 1653,1258 1693,1258 1733,1258 1493,1298 1533,1298 1573,1298 1613,1298 1653,1298 1693,1298 1733,1298 1808,1330.12 1493,1338 1533,1338 1573,1338 1613,1338 1653,1338 1693,1338 1733,1338 1493,1378 1533,1378 1573,1378 1613,1378 1653,1378 1693,1378 1733,1378 1493,1418 1533,1418 1573,1418 1613,1418 1653,1418 1693,1418 1733,1418 1493,1458 1533,1458 1573,1458 1613,1458 1653,1458 1693,1458 1733,1458 1493,1498 1533,1498 1573,1498 1613,1498 1653,1498 1693,1498 1733,1498 1908,1530.12 2108,1530.12 2308,1530.12 2508,1530.12 2708,1530.12 1408,1730.12 1608,1730.12 1808,1730.12 2008,1730.12 2208,1730.12 2408,1730.12 2608,1730.12 2108,1930.12 2308,1930.12 2508,1930.12 2708,1930.12 2008,2130.12 2208,2130.12 2408,2130.12 2608,2130.12 1508,2330.12 2308,2330.12 2708,2330.12
  other v2: 1367,1206.69 1400.08,1207.64 1384.08,1217.21 1367,1225.27 1400.08,1226.21 1384.08,1235.78 1367,1243.84 1400.08,1244.78 1384.08,1254.36 1367,1262.41 1400.08,1263.36
NC4: R2.1 U1.4 | length 1255.8
  Top Layer w10: R2.1@1084,153 1084,164.18 1105.47,185.65 1105.47,199.47 v2(1107,201) ; v2(1365,1130) 1364.91,1130.09 1364.91,1163.91 U1.4@1365,1164
  Signal Layer 1 w10: v2(1107,201) 1125,219 1320,219 1354,253 1354,945 1382,973 1382,1034 1365,1051 v2(1365,1130)
NC6: R3.1 U1.6 | length 1219.7
  Top Layer w10: R3.1@1153,160 1152.5,160.5 1152.5,199.5 v2(1153,200) ; v2(1410,1130) 1410,1154 1416,1160 1434.77,1160 1436,1161.23 U1.6@1436,1165
  Signal Layer 2 w10: v2(1153,200) 1300,200 1353,253 1353,943.97 1382,972.97 1382,1060 1410,1088 v2(1410,1130)
NetD1_2: D1.2 R1.2 | length 96.5
  Top Layer w10: D1.2 R1.2@1673.5,157
NetD2_2: D2.2 R5.1 | length 70
  Top Layer w10: D2.2 480,2283.34 R5.1@480,2341.5
NetJ3_10: J3.10 R10.2 | length 114.9
  Top Layer w10: J3.10@1398,2172 1405,2179 1405,2280.62 R10.2
NetJ3_14: J3.14 R9.2 | length 333
  Top Layer w10: J3.14 1605,2209.5 1718.5,2323 R9.2@1843,2323 ; R9.2@1846,2327 R9.2@1846.36,2326.64
NetJ3_16: J3.16 R8.1 | length 286.9
  Top Layer w10: J3.16@1707,2216 1711.5,2216 1775.5,2280 1879,2280 1921,2322 R8.1@1950,2322
NetJ3_18: J3.18 R7.2 | length 348.6
  Top Layer w10: J3.18 1805,2209.5 1851.5,2256 1945,2256 2004,2315 2052.19,2315 2059,2321.81 R7.2
NetJ3_20: J3.20 R6.2 | length 321.7
  Top Layer w10: J3.20 1956,2162 2117,2323 R6.2@2160,2323
OUT: J3.12 R4.1 R6.1 R7.1 R8.2 R9.1 U1.10 | length 2534
  Top Layer w10: U1.10 1364.91,1310.05 1364.91,1374.91 v2(1365,1375) ; J3.12 1505,2207.5 1525,2227.5 1549.5,2227.5 1590,2268 1690.62,2368.62 R9.1 ; R4.1 v1@1780,2458 ; v1(1781,2457.38) 1831.62,2457.38 1848,2441 R9.1@1848,2372 ; R9.1@1850,2368.62 2163.62,2368.62 R6.1@2164,2369
  Signal Layer 2 w10: 1363.47,1386.01 1344,1405.48 1344,1419 1344,1500 1358,1514 1358,2046 1390,2078 1390,2269 1525,2404 1593,2404 1615,2426 1768,2426 1778.13,2436.13 1778.13,2453.13 v1@1784,2459 ; 1364,1386 1364,1376 v2(1365,1375) v2@1365,1377.16
OUT_FLT: C6.2 J7.1 R4.2 TP5.1 | length 336.5
  Top Layer w10: TP5.1 1356.5,2419 1408.5,2471 1489,2471 J7.1@1503,2457 ; J7.1@1497,2457 J7.1@1503,2457 ; J7.1@1504,2456 J7.1@1503,2457 ; C6.2 1577,2409.62 1577,2457 J7.1@1503,2457
REF: J3.1 J3.3 J3.5 R10.1 U1.12 | length 1587.3
  Top Layer w10: J3.1 J3.3 1197,1966 J3.5@1199,1964 ; J3.5@1205,1974 1205,2013.5 1252.5,2061 1324,2061 1353.28,2090.28 v1(1353.28,2246.1) R10.1@1353.28,2282 ; v2@1317,1375 1317.58,1374.42 U1.12@1317.58,1309.97 ; 1317.6,1349.33 v2(1317.6,1375)
  Signal Layer 1 w10: v2@1317.6,1377.16 v2(1317.6,1375) v2@1319.13,1376.53
  Signal Layer 2 w10: v2(1317.6,1375) 1319.13,1376.53 1319.13,1398.91 1328,1407.78 1328,1510 1343,1525 1343,2071 1353.28,2081.28 v1(1353.28,2246.1)
VS: C1.1 C2.1 D1.1 D2.1 J2.1 J3.6 R11.1 TP3.1 U1.3 | length 681.7
  Top Layer w10: R11.1@535,2341.5 535,2294.34 D2.1 v2(602.49,2275) ; J3.6@1205,2188 1206,2189 v2(1206,2259) ; U1.3 1341.19,1080.81 C2.1@1345,1077 ; C1.1@1344.5,1031 C2.1@1344.5,1075.58 ; C1.1@1357.5,1021.19 1361.89,1016.8 v2(1361.89,988.19) ; TP3.1 1432,79 D1.1@1577,79 ; D1.1 1593.32,58 1705,58 J2.1
pads on no net: FID1.1 FID2.1 FID3.1 H1.0 H2.0 H3.0 H4.0 J3.7 J3.8 LBL1.0 SH-J1.0 SH-J2.0 SH-J3.0

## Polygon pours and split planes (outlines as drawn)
IS+ on Bottom Layer "BOTTOM_LAYER_IS+_P032" (solid, remove dead copper, pour order 32): 0,0 1350,0 1350,2517 0,2517
IS- on Bottom Layer "BOTTOM_LAYER_IS-_P034" (solid, remove dead copper, pour order 34): 1350,0 2760,0 2760,2517 1350,2517
IS- on Top Layer "TOP_LAYER_IS-_P028" (solid, remove dead copper, pour order 28): 1350,0 2760,0 2760,2517 1350,2517
IS+ on Top Layer "TOP_LAYER_IS+_P026" (solid, remove dead copper, pour order 26): 1.72,5 1351.72,5 1351.72,2522 1.72,2522
GND on Signal Layer 2 "SIGNAL_LAYER_2_GND_P054" (solid, remove dead copper, pour order 54): 0,0 2760,0 2760,2518 0,2517
GND on Signal Layer 2 "SIGNAL_LAYER_2_GND_P049" (solid, remove dead copper, pour order 49): 2765,-1 2758,6 2758,2514 0,2514 -14,2500 -19,2500 2,2521 12,2511 2760,2511 2760,4 2758,2 2758,-1
VS on Signal Layer 1 "SIGNAL_LAYER_1_VS_P053" (solid, remove dead copper, pour order 53): 0,0 2760,0 2760,2517 0,2517

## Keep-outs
Keep-Out Layer:
  text ".Layer_Name" at 277,-994.37 h60

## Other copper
Top Layer:
  text ".Layer_Name" at 277,-994.37 h60
Bottom Layer:
  text ".Layer_Name" at 277,-994.37 h60

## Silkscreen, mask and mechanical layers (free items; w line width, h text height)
Top Overlay:
  lines w10: 983,1647 1224,1647 ; 1382,1647 1940,1647
  text "OUT" at 1156,2437 h30
  text "Ext" at 825,2249 h30
  text "ALERT" at 330,2155 h30
  text "10 5X" at 1887,1884 h40 r270
  text "9 4X" at 1788,1850 h40 r270
  text "2 GND" at 1086,1849 h40 r270
  text "3 VS" at 1186,1849 h40 r270
  text "6" at 1489,1849 h40 r270
  text "7 2X" at 1586,1849 h40 r270
  text "8 3X" at 1688,1849 h40 r270
  text "4 NC" at 1286,1848 h40 r270
  text "5*" at 1385,1848 h40 r270
  text "1 Ext" at 985,1844 h40 r270
  text "1X" at 1490,1842 h40 r270
  text "REF" at 1050,1590 h40
  text "Gain (*Remove for 1X)" at 1376,1590 h40
  text "IS+" at 452,902 h40
  text "IS-" at 2264,898 h40
  text "DANGER HIGH VOLTAGE" at -282,604 h80
  text "CAUTION HOT SURFACE" at 1367,426 h80
  text "'.PRJ_Title' / .PRJ_Number.SCH_REV" at 63,425.62 h40
  text ".Layer_Name" at 277,-994.37 h60
Bottom Overlay:
  text ".Layer_Name" at 277,-994.37 h60
Top Paste:
  text ".Layer_Name" at 277,-994.37 h60
Bottom Paste:
  text ".Layer_Name" at 277,-994.37 h60
Top Solder:
  text ".Layer_Name" at 277,-994.37 h60
  text ".Layer_Name" at 277,-994.37 h60
Bottom Solder:
  text ".Layer_Name" at 277,-994.37 h60
Drill Guide:
  text ".Layer_Name" at 277,-994.37 h60
M1 Board Outline:
  the board outline again, w10
  text ".Layer_Name" at 277,-994.37 h60
M2 Board Dimensions:
  rectangle: -353,-547.88 -228,-422.88
  rectangle: -228,-671.88 147,-546.88
  text ".Layer_Name" at 277,-994.37 h60
M3 3D STEP Top:
  text ".Layer_Name" at 277,-994.37 h60
M4 3D STEP Bottom:
  text ".Layer_Name" at 277,-994.37 h60
M5 Assembly Top:
  text "COMPONENTS MARKED 'DNP' SHOULD NOT BE POPULATED." at 877,-370.88 h60
  text "ASSEMBLY VARIANT:" at 853,-569.88 h60
  text ".VariantName" at 1889,-569.88 h60
  text "PCB VIEWED FROM TOP SIDE" at -528.5,-791.54 h60
  text "BOARD #:" at 1948,-791.54 h60
  text ".PRJ_Number" at 2493.5,-791.54 h60
  text "REV:" at 3338,-791.54 h60
  text ".PCB_Rev" at 3629.5,-791.54 h60
  text "SVN REV:" at 4176,-791.54 h60
  text ".VersionControl_RevNumber" at 4682,-791.54 h60
  text "TID #:" at 1948,-994.88 h60
  text ".TID" at 2493.5,-994.88 h60
  text "PLOT NAME =" at -528.5,-1200.21 h60
  text ".plot_File_Name" at 277,-1200.21 h60
  text "GENERATED    :" at 1950,-1200.21 h60
  text ".Print_Date" at 2819.5,-1200.21 h60
  text ".Print_Time" at 3548.5,-1200.21 h60
  text "TEXAS INSTRUMENTS" at 4813,-1200.21 h60
M6 Assembly Bottom:
  text "COMPONENTS MARKED 'DNP' SHOULD NOT BE POPULATED." at 5773,24.12 h60
  text ".VariantName" at 4758,-569.88 h60
  text "ASSEMBLY VARIANT:" at 5797,-569.88 h60
  text ".VersionControl_RevNumber" at 735.5,-792.04 h60
  text "SVN REV:" at 1241.5,-792.04 h60
  text ".PCB_Rev" at 1788,-792.04 h60
  text "REV:" at 2079.5,-792.04 h60
  text ".PRJ_Number" at 2924,-792.04 h60
  text "BOARD #:" at 3469.5,-792.04 h60
  text "PCB VIEWED FROM BOTTOM SIDE" at 5946,-792.04 h60
  text ".TID" at 2924,-995.38 h60
  text "TID #:" at 3469.5,-995.38 h60
  text "TEXAS INSTRUMENTS" at 604.5,-1200.71 h60
  text ".Print_Time" at 1869,-1200.71 h60
  text ".Print_Date" at 2598,-1200.71 h60
  text "GENERATED    :" at 3467.5,-1200.71 h60
  text ".plot_File_Name" at 5140.5,-1200.71 h60
  text "PLOT NAME =" at 5946,-1200.71 h60
M9 Title Sheet:
  drawing of 18 lines, arcs and shapes, not listed
  text "1" at 439.84,7900.62 h70
  text "2" at 2935.5,7900.62 h70
  text "3" at 5424.84,7900.62 h70
  text "4" at 7931.51,7900.62 h70
  text "5" at 10430.5,7900.62 h70
  text "6" at 12935.5,7900.62 h70
  text "A" at -716.5,6757.62 h70
  text "A" at 14083.5,6757.62 h70
  text "B" at -716.5,4377.62 h70
  text "B" at 14083.5,4377.62 h70
  text "C" at -716.5,2002.62 h70
  text "C" at 14083.5,2002.62 h70
  text "PROJECT TITLE:" at 11043.5,141.62 h45
  text ".PRJ_Title" at 11093.5,8.3 h70
  text "DESIGNED FOR:" at 11043.5,-159.38 h45
  text ".PRJ_Customer" at 11093.5,-299.38 h70
  text "D" at -716.5,-367.38 h70
  text "D" at 14083.5,-367.38 h70
  text "FILE NAME:" at 11043.5,-459.38 h45
  text ".PCB_File_Name_No_Path" at 11093.5,-579.38 h70
  text "Texas Instruments (TI) and/or its licensors do not warrant the accuracy or completeness of this specification" at 6074,-741.22 h45
  text "ENGINEER:" at 11043.5,-749.38 h45
  text "LAYOUT BY:" at 12548.5,-749.38 h45
  text "or any information contained therein. TI and/or its licensors do not warrant that this design will meet" at 6029.01,-853.88 h45
  text ".PRJ_Engineer" at 11093.5,-904.37 h70
  text ".PCB_Layout" at 12599,-904.37 h70
  text "the specifications, will be suitable for your application or fit for any particular purpose, or will operate in" at 6029.01,-966.55 h45
  text ".Layer_Name" at 277,-994.37 h60
  text "ALTIUM DESIGNER VERSION:" at 12548.5,-1059.38 h45
  text "an implementation. TI and/or its licensors do not warrant that the design is production worthy. You should" at 6029.01,-1079.21 h45
  text "completely validate and test your design implementation to confirm the system functionality for your application." at 6074,-1191.88 h45
  text ".print_Scale" at 11093.5,-1192.7 h70
  text ".Application_BuildNumber" at 12599,-1192.7 h70
  text "1" at 439.84,-1399.38 h70
  text "2" at 2935.5,-1399.38 h70
  text "3" at 5424.84,-1399.38 h70
  text "4" at 7931.51,-1399.38 h70
  text "5" at 10430.5,-1399.38 h70
  text "6" at 12935.5,-1399.38 h70
M10 Fab Notes:
  text "DESIGN INFORMATION" at 12082.02,6220.3 h60
  text "MIN. TRACK WIDTH:" at 11437.46,6088.17 h60
  text "8" at 12533.7,6088.17 h60
  text "MIL" at 12688.46,6088.17 h60
  text "mm" at 12812,5968.12 h60
  text "MIN. CLEARANCE:" at 11437.46,5964.04 h60
  text "0.127" at 12473.7,5964.05 h60
  text "MIN. VIA PAD SIZE:" at 11437.46,5839.92 h60
  text "18" at 12503.71,5839.92 h60
  text "MIL" at 12688.46,5839.92 h60
  text "5 MIL" at 12132.46,5710.02 h60
  text "MINIMUM ANNULAR RING" at 11108.23,5701.8 h60
  text "EXTERNAL" at 12840.46,5701.8 h60
  text "PER" at 11308.23,5591.67 h60
  text "IPC-D-275 CLASS 2 LEVEL C" at 11528.23,5591.67 h60
  text "MIL, HOLES" at 13016.46,5491.19 h60
  text "+/-" at 12624,5482.61 h60
  text "+/-" at 13478,5482.61 h60
  text "REGISTRATION TOLERANCES:" at 11108.23,5481.54 h60
  text "METAL" at 12308,5481.54 h60
  text "5" at 12884.2,5481.54 h60
  text "3" at 13717.2,5481.54 h60
  text "MIL" at 13833.46,5481.54 h60
  text "HOLE SIZE TOLERANCE (UNLESS OTHERWISE SPECIFIED):" at 11108.23,5383.23 h60
  text "+/-" at 13478,5380.35 h60
  text "3" at 13717.2,5379.29 h60
  text "MIL" at 13833.46,5379.29 h60
  text "MATERIAL:" at 11033.46,5241.64 h60
  text "FR-4 High Tg" at 12019.9,5113.12 h60
  text "X" at 11875.46,5105.13 h60
  text "FR-408" at 11454.46,5100.61 h60
  text "OTHER" at 12942.46,5100.61 h60
  text "63 MIL (1.6mm) +/-10%" at 11774.56,4957.58 h60
  text "X" at 11654.46,4955.13 h60
  text "THICKNESS:" at 11108.23,4949.36 h60
  text "OTHER" at 13059.46,4949.36 h60
  text "TOLERANCE:" at 11108.23,4811.05 h60
  text "X" at 11956.46,4811.05 h60
  text "ANSI IPC-6012 TYPE 3 CLASS 2" at 12134.48,4811.05 h60
  text "OTHER +/-" at 12134.46,4666.86 h60
  text "BOW & TWIST:" at 11108.23,4521.67 h60
  text "X" at 11956.46,4521.67 h60
  text "ANSI IPC-6012 TYPE 3 CLASS 2" at 12134.48,4521.67 h60
  text "OTHER +/-" at 12134.46,4374.97 h60
  text "DRILLING:" at 11033.46,4244.35 h60
  text "NC_DRILL FILES" at 12794.46,4139.16 h60
  text "REFERENCE:" at 11108.23,4135.23 h60
  text "X" at 11765.46,4135.13 h60
  text "AS SHOWN" at 11943.46,4135.23 h60
  text "X" at 12666.46,4135.23 h60
  text "OTHER" at 13092.46,3992.97 h60
  text "PTH COPPER THICKNESS:" at 11107.91,3989.45 h60
  text "X" at 12247.14,3989.45 h60
  text "20-30 um" at 12375.14,3989.45 h60
  text "BOARD FINISH:" at 11033.46,3841.85 h60
  text "SILKSCREEN:" at 11188.68,3731.72 h60
  text "X" at 12146.46,3731.72 h60
  text "TOP" at 12263.46,3731.72 h60
  text "X" at 12656.46,3731.72 h60
  text "BOTTOM" at 12774.46,3731.72 h60
  text "SILKSCREEN COLOR:" at 11188.68,3576.53 h60
  text "X" at 12145.46,3576.53 h60
  text "WHITE" at 12263.46,3576.53 h60
  text "OTHER" at 12774.46,3576.53 h60
  text "X" at 12276.46,3433.09 h60
  text "GREEN" at 12394.46,3433.09 h60
  text "OTHER" at 13012.46,3433.09 h60
  text "SOLDER RESIST COLOR:" at 11188.68,3426.22 h60
  text "X" at 12276.46,3278.83 h60
  text "MATTE" at 12394.46,3278.83 h60
  text "SEMI-GLOSS" at 13012,3278.2 h60
  text "IMMERSION GOLD (ENIG)" at 12094.46,3106.06 h60
  text "ENEPIG" at 13432,3098.84 h60
  text "SURFACE FINISH:" at 11033.46,3097.84 h60
  text "X" at 11916.46,3097.84 h60
  text "IMM. TIN/SILVER OR EQUIV" at 11363,2960.53 h60
  text "OTHER" at 12794.46,2956.59 h60
  text "ARRAY/PANEL:" at 11033.46,2801.21 h60
  text "CUT AND TRIM PER M1 BOARD OUTLINE" at 12094.46,2792.99 h60
  text "N.C. ROUTE" at 12094.46,2657.02 h60
  text "X" at 12782.46,2657.02 h60
  text "V. SCORE" at 12960.46,2657.02 h60
  text "CERTIFICATION:" at 11033.46,2527.9 h60
  text "MATERIALS AND WORKMANSHIP FOR ALL PCBS" at 11758.46,2527.9 h60
  text "TO MEET OR EXCEED THE REQUIREMENTS OF:" at 11758.46,2433.83 h60
  text "X" at 11395.97,2305.2 h60
  text "ANSI IPC-A-600F CLASS ->" at 11523.96,2305.2 h60
  text "X" at 13171.97,2305.2 h60
  text "2" at 13281.96,2305.2 h60
  text "1" at 12966.96,2303.71 h60
  text "3" at 13635.96,2303.71 h60
  text "X" at 12207.97,2157.52 h60
  text "RoHS" at 12335.96,2157.52 h60
  text "OTHER" at 12980.36,2157.52 h60
  text "PER ORDER" at 13377.42,2157.52 h60
  text "ALL BOARDS MUST MEET OR EXCEED UL94-V0 REQUIREMENTS." at 11061,2003.69 h60
  text "PCB MUST BEAR THE UL94V-0 UL REGISTERED MATERIAL ID NUMBER" at 11061,1887.63 h60
  text "ADDITIONAL REQUIREMENTS:" at 11033.46,1718.2 h60
  text "MICROSECTION:" at 11108.23,1611.08 h60
  text "NO" at 12013.96,1611.08 h60
  text "X" at 12321,1479.12 h60
  text "REQUIRED" at 12875.46,1466.74 h60
  text "BARE BOARD ELEC. TEST:" at 11108.23,1463.89 h60
  text "NONE" at 12413.96,1463.89 h60
  text "PER ORDER" at 13467.46,1463.89 h60
  text "No VIAS REQUIRE NON-CONDUCTIVE FILL AND PLANARIZE" at 11276.38,1258.94 h59
  text "No VIAS REQUIRE CONDUCTIVE FILL AND PLANARIZE" at 11284.38,1154.97 h60
  text "OUTER XX MIL TRACES REQUIRE 50 OHM SINGLE-ENDED IMPEDANCE" at 11283.39,991.58 h58
  text "LAYER 2 & 3 (INNER LAYERS) 17 MIL WIDE, XX MIL SPACE / TRACES REQUIRE 100 OHM DIFFERENTIAL IMPEDANCE" at 11237,649.12 h60 r0.3
  text ".Layer_Name" at 277,-994.37 h60
M11 Gerber Information:
  text "ALL ARTWORK VIEWED FROM TOP SIDE" at -528.5,-791.54 h60
  text "BOARD #:" at 1948,-791.54 h60
  text ".PRJ_Number" at 2493.5,-791.54 h60
  text "REV:" at 3338,-791.54 h60
  text ".PCB_Rev" at 3629.5,-791.54 h60
  text "SVN REV:" at 4176,-791.54 h60
  text ".VersionControl_RevNumber" at 4682,-791.54 h60
  text "LAYER NAME =" at -528.5,-994.37 h60
  text "TID #:" at 1948,-994.88 h60
  text ".TID" at 2493.5,-994.88 h60
  text "PLOT NAME =" at -528.5,-1200.21 h60
  text ".plot_File_Name" at 277,-1200.21 h60
  text "GENERATED    :" at 1950,-1200.21 h60
  text ".Print_Date" at 2819.5,-1200.21 h60
  text ".Print_Time" at 3548.5,-1200.21 h60
  text "TEXAS INSTRUMENTS" at 4813,-1200.21 h60
M12 Stackup:
  drawing of 444 lines, arcs and shapes, not listed
  text "Layer" at 6413.09,5230.71 h60
  text "Name" at 6823,5230.71 h60
  text "Material" at 7762.74,5230.71 h60
  text "Thickness" at 8622.51,5230.71 h60
  text "Constant" at 9272.34,5230.71 h60
  text "Board Layer Stack" at 9842.2,5230.71 h60
  text "Top Overlay" at 6823,5110.71 h60
  text "Top Solder" at 6823,4990.71 h60
  text "Solder Resist" at 7762.74,4990.71 h60
  text "0.40mil" at 8622.51,4990.71 h60
  text "3.5" at 9272.34,4990.71 h60
  text "1" at 6413.09,4870.71 h60
  text "Top Layer" at 6823,4870.71 h60
  text "2.80mil" at 8622.51,4870.71 h60
  text "Dielectric1" at 6823,4750.71 h60
  text "FR-4" at 7762.74,4750.71 h60
  text "17.00mil" at 8622.51,4750.71 h60
  text "4.2" at 9272.34,4750.71 h60
  text "2" at 6413.09,4630.71 h60
  text "Signal Layer 1" at 6823,4630.71 h60
  text "2.80mil" at 8622.51,4630.71 h60
  text "Dielectric 2" at 6823,4510.71 h60
  text "FR-4" at 7762.74,4510.71 h60
  text "17.00mil" at 8622.51,4510.71 h60
  text "4.2" at 9272.34,4510.71 h60
  text "3" at 6413.09,4390.71 h60
  text "Signal Layer 2" at 6823,4390.71 h60
  text "2.80mil" at 8622.51,4390.71 h60
  text "Dielectric 3" at 6823,4270.71 h60
  text "FR-4" at 7762.74,4270.71 h60
  text "17.00mil" at 8622.51,4270.71 h60
  text "4.2" at 9272.34,4270.71 h60
  text "4" at 6413.09,4150.71 h60
  text "Bottom Layer" at 6823,4150.71 h60
  text "2.80mil" at 8622.51,4150.71 h60
  text "Bottom Solder" at 6823,4030.71 h60
  text "Solder Resist" at 7762.74,4030.71 h60
  text "0.40mil" at 8622.51,4030.71 h60
  text "3.5" at 9272.34,4030.71 h60
  text "Bottom Overlay" at 6823,3910.71 h60
  text ".Layer_Name" at 277,-994.37 h60
M13 Component Bodies Top:
  text ".Layer_Name" at 277,-994.37 h60
M14 Component Bodies Bottom:
  text ".Layer_Name" at 277,-994.37 h60
M15 Courtyards Top:
  text ".Layer_Name" at 277,-994.37 h60
M16 Courtyards Bottom:
  text ".Layer_Name" at 277,-994.37 h60
Drill Drawing:
  lines w10: 3034.09,3237.74 3061.72,3251.55 3089.34,3237.74 3075.53,3265.37 3089.34,3292.99 3061.72,3279.18 3034.09,3292.99 3047.9,3265.37 3034.09,3237.74 ; 3034.09,3375.87 3047.9,3375.87 3047.9,3362.06 3075.53,3362.06 3075.53,3375.87 3089.34,3375.87 3089.34,3403.5 3075.53,3403.5 3075.53,3417.31 3047.9,3417.31 3047.9,3403.5 3034.09,3403.5 3034.09,3375.87 ; 3034.09,3486.38 3089.34,3486.38 3089.34,3541.63 3034.09,3541.63 3034.09,3486.38 ; 3034.09,3665.95 3089.34,3665.95 3061.72,3610.7 3034.09,3665.95 ; 3034.09,3735.02 3034.09,3748.83 3047.9,3762.65 3034.09,3776.46 3034.09,3790.27 3047.9,3790.27 3061.72,3776.46 3075.53,3790.27 3089.34,3790.27 3089.34,3776.46 3075.53,3762.65 3089.34,3748.83 3089.34,3735.02 3075.53,3735.02 3061.72,3748.83 3047.9,3735.02 3034.09,3735.02
  lines w12: 2984,3200.44 6141.36,3200.44 ; 2984,3822.04 6141.36,3822.04 ; 3321.86,3076.12 3321.86,3946.36 ; 3623.5,3076.12 3623.5,3946.36 ; 4216.3,3076.12 4216.3,3946.36 ; 4475.44,3076.12 4475.44,3946.36 ; 4850.6,3076.12 4850.6,3946.36 ; 5574.93,3076.12 5574.93,3946.36 ; 2984,3076.12 6141.36,3076.12 6141.36,3946.36 2984,3946.36 2984,3076.12
  text "Symbol" at 3058.59,3859.34 h72
  text "Count" at 3359.16,3859.34 h72
  text "Hole Size" at 3660.8,3859.34 h72
  text "Plated" at 4253.6,3859.34 h72
  text "Hole Type" at 4512.74,3859.34 h72
  text "Drill Layer Pair" at 4887.89,3859.34 h72
  text "Hole Tolerance" at 5612.22,3859.34 h72
  text "38" at 3359.16,3735.02 h60
  text "8.00mil (0.203mm)" at 3660.8,3735.02 h60
  text "PTH" at 4253.6,3735.02 h60
  text "Round" at 4512.74,3735.02 h60
  text "Top Layer - Bottom Layer" at 4887.89,3735.02 h60
  text "302" at 3359.16,3610.7 h60
  text "15.00mil (0.381mm)" at 3660.8,3610.7 h60
  text "PTH" at 4253.6,3610.7 h60
  text "Round" at 4512.74,3610.7 h60
  text "Top Layer - Bottom Layer" at 4887.89,3610.7 h60
  text "5" at 3359.16,3486.38 h60
  text "51.97mil (1.320mm)" at 3660.8,3486.38 h60
  text "PTH" at 4253.6,3486.38 h60
  text "Round" at 4512.74,3486.38 h60
  text "Top Layer - Bottom Layer" at 4887.89,3486.38 h60
  text "4" at 3359.16,3362.06 h60
  text "145.00mil (3.683mm)" at 3660.8,3362.06 h60
  text "PTH" at 4253.6,3362.06 h60
  text "Round" at 4512.74,3362.06 h60
  text "Top Layer - Bottom Layer" at 4887.89,3362.06 h60
  text "2" at 3359.16,3237.74 h60
  text "263.78mil (6.700mm)" at 3660.8,3237.74 h60
  text "NPTH" at 4253.6,3237.74 h60
  text "Round" at 4512.74,3237.74 h60
  text "Top Layer - Bottom Layer" at 4887.89,3237.74 h60
  text "351 Total" at 3359.16,3113.42 h60
  text ".Layer_Name" at 277,-994.37 h60
M17 Embedded Cavity:
  text ".Layer_Name" at 277,-994.37 h60
M18 Embedded Assembly:
  text ".Layer_Name" at 277,-994.37 h60
M19 Embedded Keepout:
  text ".Layer_Name" at 277,-994.37 h60

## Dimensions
-56,2516 to -1,-1 on M2 Board Dimensions
0,2531 to 2760,2528 on M2 Board Dimensions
